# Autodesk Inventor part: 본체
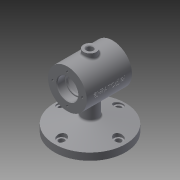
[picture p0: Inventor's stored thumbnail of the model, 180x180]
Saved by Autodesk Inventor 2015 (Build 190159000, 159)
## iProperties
Created: 2018-12
Part Number: 본체
Material: 일반
Document SubType Name: Modeling
Designer: now
Density: 1 g/cm^3
Appearance: 기본값
Author: now
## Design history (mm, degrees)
sketch "스케치1"
  geometry: L1 (0, 0)-(0, -25.737); L2 (0, 0)-(-55, -14.737); L3 (0, -25.737)-(-55, -25.737); L4 (-55, -14.737)-(-55, -25.737)
  constraints: 8 end point, 2 vertical, 1 horizontal
  dimensions: "d0" = 11 distance of L2.end L3.end; "d1" = 55 distance of L1.end L3.end; "d3" = 75 deg angle of L4 L2
revolve "회전1" sketch "스케치1" stored, may be unused: angle "d4" = 90 deg
sketch "스케치2"
  geometry: C1 r 55 at (0, 0) reference; C2 r 12 at (0, 0)
  constraints: 1 centre point, 1 coincident
  dimensions: "d5" = 24 diameter of C2
extrude "돌출1" join sketch "스케치2" distance "d6" = 75; taper "d7" = 0 deg
sketch "스케치3"
  geometry: L1 (-35, 79.263)-(35, 79.263); L2 (35, 79.263)-(35, 49.263); L3 (35, 49.263)-(-35, 49.263); L4 (-35, 49.263)-(-35, 79.263); L5 (12, 49.263)-(-12, 49.263) reference; 2 further points
  constraints: 8 end point, 2 midpoint, 2 parallel, 1 horizontal, 1 perpendicular
  dimensions: "d9" = 60 diameter of L1 L3; "d10" = 35 distance of L3.end point (0, 49.263); "d11" = 70 distance of L1.start L1.end
revolve "회전2" sketch "스케치3" stored, may be unused: angle "d12" = 90 deg
node "작업 평면1"
sketch "스케치4"
  geometry: C1 r 10 at (0, 0); 1 further point
  constraints: 1 centre point, 1 coincident
  dimensions: "d14" = 20 diameter of C1
extrude "돌출2" join sketch "스케치4" stored distance "d15" = 75; taper "d16" = 0 deg
sketch "스케치5"
  geometry: L1 (-35, 19.263)-(-35, 79.263) reference; L2 (-35, 49.263)-(35, 49.263); L3 (35, 19.263)-(35, 79.263) reference; L4 (-35, 65.263)-(-23.3, 65.263); L5 (-23, 64.963)-(-23, 63.263); L6 (-23, 63.263)-(-20, 63.263); L7 (-20, 63.263)-(-20, 71.263); L8 (-17, 74.263)-(17, 74.263); L9 (20, 71.263)-(20, 63.263); L10 (20, 63.263)-(23, 63.263); L11 (23, 63.263)-(23, 64.963); L12 (23.3, 65.263)-(35, 65.263); A1 r 3 centre (-17, 71.263) between (-17, 74.263) and (-20, 71.263); A2 r 3 centre (17, 71.263) between (20, 71.263) and (17, 74.263); A3 r 0.3 centre (-23.3, 64.963) between (-23, 64.963) and (-23.3, 65.263); A4 r 0.3 centre (23.3, 64.963) between (23.3, 65.263) and (23, 64.963); 5 further points
  constraints: 20 end point, 14 point on line, 8 point on circle, 8 tangent, 4 centre point, 4 vertical, 3 horizontal, 2 equal radius, 2 midpoint
  dimensions: "d17" = 32 diameter of L4 L2; "d18" = 28 diameter of L6 L2; "d19" = 50 diameter of L8 L2; "d20" = 12 distance of L4.start point (-23, 65.263); "d21" = 3 distance of L5.end L6.end; "d22" = 40 distance of point (-20, 74.263) point (20, 74.263); "d23" = 3 distance of L9.end L10.end; "d24" = 3 radius of A1; "d25" = 0.3 radius of A3
revolve "회전3" sketch "스케치5" stored, may be unused: angle "d26" = 90 deg
sketch "스케치6"
  geometry: C1 r 10 at (0, 0) reference; C2 r 5 at (0, 0)
  constraints: 1 centre point, 1 coincident
  dimensions: "d27" = 10 diameter of C2
extrude "돌출3" cut sketch "스케치6" stored distance "d28" = 75; taper "d29" = 0 deg
sketch "스케치7" dims "d30" = 88
  geometry: C1 r 55 at (0, 0) reference; C2 r 4.5 at (-44, 0); 1 further point
  constraints: 2 horizontal alignment, 1 centre point, 1 coincident, 2 other
  dimensions: "d31" = 9 diameter of C2
extrude "돌출4" cut sketch "스케치7" distance "d32" = 10; taper "d33" = 0 deg
sketch "스케치8"
  geometry: C1 r 4.5 at (0, 0) reference; C2 r 7 at (0, 0); 1 further point
  constraints: 1 centre point, 1 coincident
  dimensions: "d34" = 14 diameter of C2
extrude "돌출5" cut sketch "스케치8" distance "d35" = 10; taper "d36" = 0 deg
fillet "모깎기1" dims "d40" = 3
chamfer "모따기1" distance "d41" = 1; stored, may be unused: second distance "d42" = 2, angle "d43" = 45 deg
chamfer "모따기2" distance "d44" = 1; stored, may be unused: second distance "d45" = 2, angle "d46" = 45 deg
sketch "스케치9"
  geometry: C1 r 30 at (0, 0) reference; 2 further points
  constraints: 1 vertical alignment
  dimensions: "d47" = 23 distance of C1.centre point (0, 23)
hole "구멍1" sketch "스케치9" at (0, 23) diameter "d48" = 3.242; stored, may be unused: countersink angle "d52" = 90 deg, drill point angle "d54" = 118 deg; dims "d49" = 8, "d50" = 4, "d51" = 2, "d53" = 10
sketch "스케치10"
  geometry: C1 r 30 at (0, 0) reference; 2 further points
  constraints: 1 vertical alignment
  dimensions: "d58" = 23 distance of C1.centre point (0, -23)
hole "구멍2" sketch "스케치10" at (0, -23) diameter "d59" = 3.242; stored, may be unused: countersink angle "d63" = 90 deg, drill point angle "d65" = 118 deg; dims "d60" = 8, "d61" = 4, "d62" = 2, "d64" = 10
fillet "모깎기2" dims "d69" = 3
node "작업 평면2"
sketch "스케치11"
  geometry: L1 (-35, 19.263)-(-35, 79.263) reference; 2 further points
  constraints: 1 other
  dimensions: "d71" = 35 distance from line of L1 point (0, 49.263); "d72" = 30 vertical distance of L1.end point (0, 49.263)
feature "엠보싱1" sketch "스케치11" dims "d0" = 11, "d1" = 55, "d3" = 75 deg, "d73" = 0.5, "d74" = 0
node "솔리드1"
pattern_circular "원형 패턴1" dims angle "d38" = 360 deg
pattern_circular "원형 패턴2" dims angle "d56" = 360 deg
pattern_circular "원형 패턴3" dims angle "d67" = 360 deg
other parameters: "d13" = -112, "d70" = 45.75
